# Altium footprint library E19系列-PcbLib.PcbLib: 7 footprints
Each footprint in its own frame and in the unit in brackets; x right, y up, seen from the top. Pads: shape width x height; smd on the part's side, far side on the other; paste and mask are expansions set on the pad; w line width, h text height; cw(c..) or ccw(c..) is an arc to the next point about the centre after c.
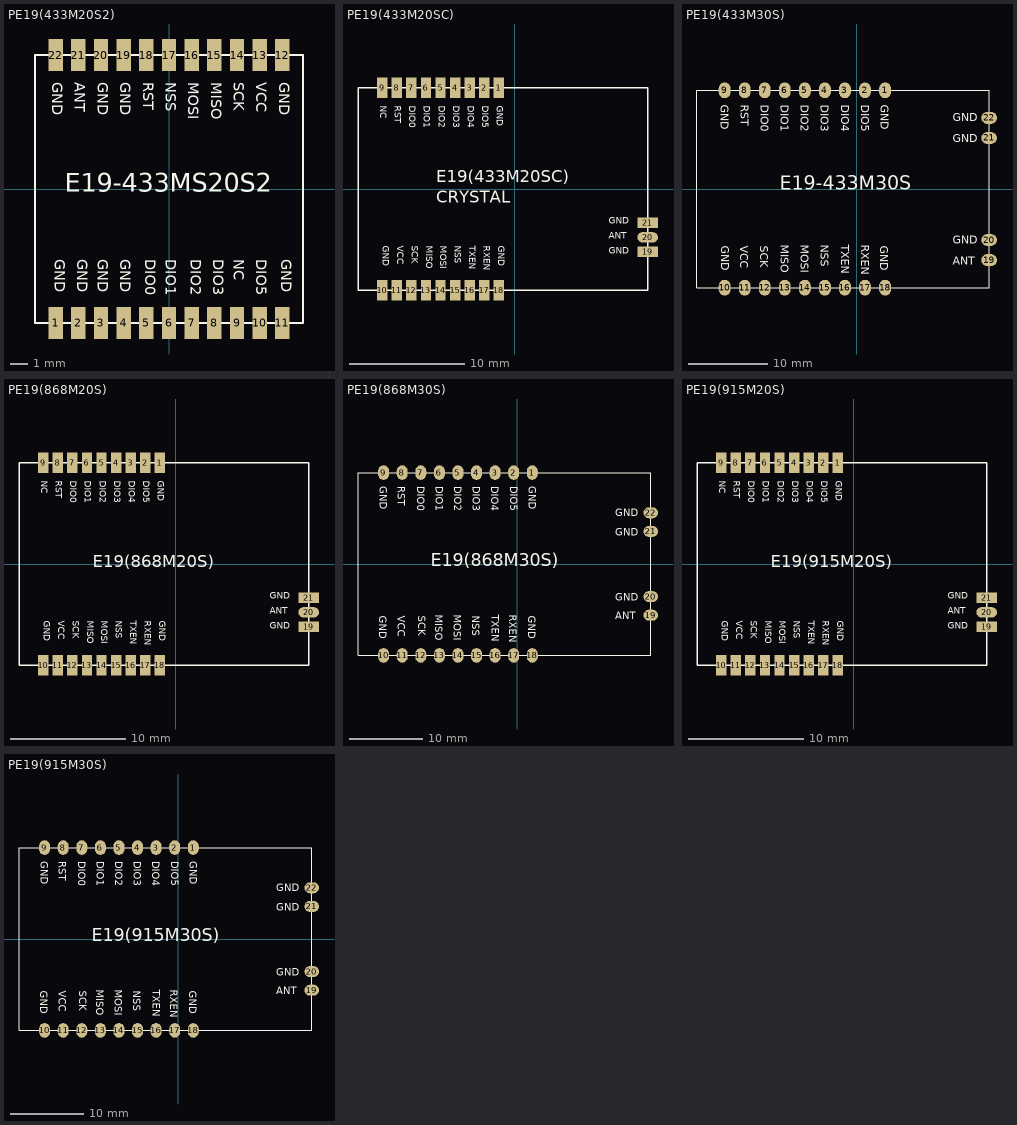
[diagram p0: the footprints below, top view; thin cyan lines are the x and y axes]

## PE19(433M20S2) [mm] "15mm*15mm*2.6mm-S"
pads (22):
  rect 0.8x1.8 smd: 1(-6.35,-7.5) 2(-5.08,-7.5) 3(-3.81,-7.5) 4(-2.54,-7.5) 5(-1.27,-7.5) 6(0,-7.5) 7(1.275,-7.5) 8(2.54,-7.5) 9(3.81,-7.5) 10(5.08,-7.5) 11(6.35,-7.5) 12(6.35,7.5) 13(5.08,7.5) 14(3.81,7.5) 15(2.54,7.5) 16(1.27,7.5) 17(0,7.5) 18(-1.275,7.5) 19(-2.54,7.5) 20(-3.81,7.5) 21(-5.08,7.5) 22(-6.35,7.5)
Top Overlay:
  lines w0.127: -7.5,-7.5 7.5,-7.5 7.5,7.5 -7.5,7.5 -7.5,-7.5
  text "E19-433MS20S2" at -5.842,-0.508 h1.8
  text "GND" at -6.604,-3.937 h1
  text "GND" at -5.334,-3.937 h1
  text "GND" at -4.191,-3.937 h1
  text "GND" at -2.921,-3.937 h1
  text "DIO0" at -1.524,-3.937 h1
  text "DIO1" at -0.381,-3.937 h1
  text "DIO2" at 1.016,-3.937 h1
  text "DIO3" at 2.286,-3.937 h1
  text "NC" at 3.429,-3.937 h1
  text "DIO5" at 4.699,-3.937 h1
  text "GND" at -6.731,5.969 h1
  text "ANT" at -5.461,5.969 h1
  text "GND" at -4.191,5.969 h1
  text "GND" at -2.921,5.969 h1
  text "RST" at -1.651,5.969 h1
  text "NSS" at -0.381,5.969 h1
  text "MISO" at 2.159,5.969 h1
  text "SCK" at 3.429,5.969 h1
  text "VCC" at 4.699,5.969 h1
  text "GND" at 5.969,5.969 h1
  text "GND" at 6.096,-3.937 h1
  text "MOSI" at 0.889,5.969 h1

## PE19(433M20SC) [mm] "25.2mm*17.6mm*3.8mm-S"
pads (21):
  rect 0.9x1.8 smd: 1(-1.39,8.8) 2(-2.66,8.8) 3(-3.93,8.8) 4(-5.2,8.8) 5(-6.47,8.8) 6(-7.74,8.8) 7(-9.01,8.8) 8(-10.28,8.8) 9(-11.55,8.8) 10(-11.55,-8.8) 11(-10.28,-8.8) 12(-9.01,-8.8) 13(-7.74,-8.8) 14(-6.47,-8.8) 15(-5.2,-8.8) 16(-3.93,-8.8) 17(-2.66,-8.8) 18(-1.39,-8.8)
  rect 1.8x0.9 smd: 19(11.55,-5.47) 21(11.55,-2.93)
  oval 1.8x0.9 smd: 20(11.55,-4.2)
Top Overlay:
  lines w0.127: -13.65,-8.8 11.55,-8.8 11.55,8.8 -13.65,8.8 -13.65,-8.8
  text "CRYSTAL" at -6.858,-1.524 h1.8
  text "E19(433M20SC)" at -6.858,0.254 h1.8
  text "GND" at -11.707,-4.924 h1
  text "VCC" at -10.455,-4.924 h1
  text "SCK" at -9.202,-4.924 h1
  text "MISO" at -7.95,-4.924 h1
  text "MOSI" at -6.697,-4.924 h1
  text "NSS" at -5.445,-4.924 h1
  text "TXEN" at -4.192,-4.924 h1
  text "RXEN" at -2.94,-4.924 h1
  text "GND" at -1.687,-4.924 h1
  text "NC" at -11.938,7.239 h1
  text "GND" at 8.158,-3.22 h1
  text "RST" at -10.668,7.239 h1
  text "DIO0" at -9.398,7.239 h1
  text "DIO1" at -8.128,7.239 h1
  text "DIO2" at -6.858,7.239 h1
  text "DIO3" at -5.588,7.239 h1
  text "DIO4" at -4.318,7.239 h1
  text "DIO5" at -3.048,7.239 h1
  text "GND" at -1.778,7.239 h1
  text "ANT" at 8.158,-4.53 h1
  text "GND" at 8.158,-5.84 h1

## PE19(433M30S) [mm]
pads (22):
  oval 1.5x2 smd: 1(3.57,12.5) 2(1.03,12.5) 3(-1.51,12.5) 4(-4.05,12.5) 5(-6.59,12.5) 6(-9.13,12.5) 7(-11.67,12.5) 8(-14.21,12.5) 9(-16.75,12.5) 10(-16.75,-12.5) 11(-14.21,-12.5) 12(-11.67,-12.5) 13(-9.13,-12.5) 14(-6.59,-12.5) 15(-4.05,-12.5) 16(-1.51,-12.5) 17(1.03,-12.5) 18(3.57,-12.5)
  oval 2x1.5 smd: 19(16.75,-9) 20(16.75,-6.46) 21(16.75,6.46) 22(16.75,9)
Top Overlay:
  lines w0.127: -20.25,-12.5 -20.25,12.5 16.75,12.5 16.75,-12.5 -20.25,-12.5
  text "GND" at 12.135,5.915 h1
  text "GND" at 12.135,8.582 h1
  text "ANT" at 12.135,-9.579 h1
  text "GND" at 12.135,-6.912 h1
  text "GND" at -17.25,10.691 h1
  text "RST" at -14.71,10.691 h1
  text "DIO0" at -12.17,10.691 h1
  text "DIO1" at -9.63,10.691 h1
  text "DIO2" at -7.09,10.691 h1
  text "DIO3" at -4.55,10.691 h1
  text "DIO4" at -2.01,10.691 h1
  text "DIO5" at 0.53,10.691 h1
  text "RXEN" at 0.53,-7.079 h1
  text "TXEN" at -2.01,-7.079 h1
  text "NSS" at -4.55,-7.079 h1
  text "MOSI" at -7.09,-7.079 h1
  text "MISO" at -9.63,-7.079 h1
  text "SCK" at -12.249,-7.166 h1
  text "VCC" at -14.789,-7.166 h1
  text "GND" at -17.202,-7.166 h1
  text "E19-433M30S" at -9.779,-0.635 h3
  text "GND" at 2.991,-7.166 h1
  text "GND" at 3.04,10.691 h1

## PE19(868M20S) [mm] "25.2mm*17.6mm*3.5mm-S"
pads (21):
  rect 0.9x1.8 smd: 1(-1.39,8.8) 2(-2.66,8.8) 3(-3.93,8.8) 4(-5.2,8.8) 5(-6.47,8.8) 6(-7.74,8.8) 7(-9.01,8.8) 8(-10.28,8.8) 9(-11.55,8.8) 10(-11.55,-8.8) 11(-10.28,-8.8) 12(-9.01,-8.8) 13(-7.74,-8.8) 14(-6.47,-8.8) 15(-5.2,-8.8) 16(-3.93,-8.8) 17(-2.66,-8.8) 18(-1.39,-8.8)
  rect 1.8x0.9 smd: 19(11.55,-5.47) 21(11.55,-2.93)
  oval 1.8x0.9 smd: 20(11.55,-4.2)
Top Overlay:
  lines w0.127: -13.65,-8.8 11.55,-8.8 11.55,8.8 -13.65,8.8 -13.65,-8.8
  text "E19(868M20S)" at -7.239,-0.635 h1.8
  text "GND" at -11.707,-4.924 h1
  text "VCC" at -10.455,-4.924 h1
  text "SCK" at -9.202,-4.924 h1
  text "MISO" at -7.95,-4.924 h1
  text "MOSI" at -6.697,-4.924 h1
  text "NSS" at -5.445,-4.924 h1
  text "TXEN" at -4.192,-4.924 h1
  text "RXEN" at -2.94,-4.924 h1
  text "GND" at -1.687,-4.924 h1
  text "NC" at -11.938,7.239 h1
  text "GND" at 8.158,-3.22 h1
  text "RST" at -10.668,7.239 h1
  text "DIO0" at -9.398,7.239 h1
  text "DIO1" at -8.128,7.239 h1
  text "DIO2" at -6.858,7.239 h1
  text "DIO3" at -5.588,7.239 h1
  text "DIO4" at -4.318,7.239 h1
  text "DIO5" at -3.048,7.239 h1
  text "GND" at -1.778,7.239 h1
  text "ANT" at 8.158,-4.53 h1
  text "GND" at 8.158,-5.84 h1

## PE19(868M30S) [mm] "40mm*25mm*4.85mm-S"
pads (22):
  oval 1.5x2 smd: 1(2.07,12.5) 2(-0.47,12.5) 3(-3.01,12.5) 4(-5.55,12.5) 5(-8.09,12.5) 6(-10.63,12.5) 7(-13.17,12.5) 8(-15.71,12.5) 9(-18.25,12.5) 10(-18.25,-12.5) 11(-15.71,-12.5) 12(-13.17,-12.5) 13(-10.63,-12.5) 14(-8.09,-12.5) 15(-5.55,-12.5) 16(-3.01,-12.5) 17(-0.47,-12.5) 18(2.07,-12.5)
  oval 2x1.5 smd: 19(18.25,-7) 20(18.25,-4.46) 21(18.25,4.46) 22(18.25,7)
Top Overlay:
  lines w0.127: -21.75,-12.5 18.25,-12.5 18.25,12.5 -21.75,12.5 -21.75,-12.5
  text "ANT" at 13.429,-7.547 h1
  text "GND" at 13.429,-5.007 h1
  text "GND" at 13.429,3.883 h1
  text "GND" at 13.429,6.55 h1
  text "RXEN" at -1.049,-6.912 h1
  text "TXEN" at -3.462,-6.912 h1
  text "NSS" at -6.129,-7.039 h1
  text "MOSI" at -8.669,-6.912 h1
  text "MISO" at -11.209,-6.912 h1
  text "SCK" at -13.495,-7.039 h1
  text "VCC" at -16.289,-7.039 h1
  text "GND" at -18.829,-7.039 h1
  text "DIO5" at -0.97,10.614 h1
  text "DIO4" at -3.51,10.614 h1
  text "DIO3" at -6.05,10.614 h1
  text "DIO2" at -8.59,10.614 h1
  text "DIO1" at -11.13,10.614 h1
  text "DIO0" at -13.67,10.614 h1
  text "RST" at -16.289,10.614 h1
  text "GND" at -18.75,10.614 h1
  text "GND" at 1.6,10.614 h1
  text "GND" at 1.491,-7.039 h1
  text "E19(868M30S)" at -11.811,-0.889 h3

## PE19(915M20S) [mm] "25.2mm*17.6mm*3.5mm-S"
pads (21):
  rect 0.9x1.8 smd: 1(-1.39,8.8) 2(-2.66,8.8) 3(-3.93,8.8) 4(-5.2,8.8) 5(-6.47,8.8) 6(-7.74,8.8) 7(-9.01,8.8) 8(-10.28,8.8) 9(-11.55,8.8) 10(-11.55,-8.8) 11(-10.28,-8.8) 12(-9.01,-8.8) 13(-7.74,-8.8) 14(-6.47,-8.8) 15(-5.2,-8.8) 16(-3.93,-8.8) 17(-2.66,-8.8) 18(-1.39,-8.8)
  rect 1.8x0.9 smd: 19(11.55,-5.47) 21(11.55,-2.93)
  oval 1.8x0.9 smd: 20(11.55,-4.2)
Top Overlay:
  lines w0.127: -13.65,-8.8 -13.65,8.8 11.55,8.8 11.55,-8.8 -13.65,-8.8
  text "GND" at 8.158,-5.84 h1
  text "ANT" at 8.158,-4.53 h1
  text "GND" at -1.778,7.239 h1
  text "DIO5" at -3.048,7.239 h1
  text "DIO4" at -4.318,7.239 h1
  text "DIO3" at -5.588,7.239 h1
  text "DIO2" at -6.858,7.239 h1
  text "DIO1" at -8.128,7.239 h1
  text "DIO0" at -9.398,7.239 h1
  text "RST" at -10.668,7.239 h1
  text "GND" at 8.158,-3.22 h1
  text "NC" at -11.938,7.239 h1
  text "GND" at -1.687,-4.924 h1
  text "RXEN" at -2.94,-4.924 h1
  text "TXEN" at -4.192,-4.924 h1
  text "NSS" at -5.445,-4.924 h1
  text "MOSI" at -6.697,-4.924 h1
  text "MISO" at -7.95,-4.924 h1
  text "SCK" at -9.202,-4.924 h1
  text "VCC" at -10.455,-4.924 h1
  text "GND" at -11.707,-4.924 h1
  text "E19(915M20S)" at -7.239,-0.635 h1.8

## PE19(915M30S) [mm] "40mm*25mm*4.85mm-S"
pads (22):
  oval 1.5x2 smd: 1(2.07,12.5) 2(-0.47,12.5) 3(-3.01,12.5) 4(-5.55,12.5) 5(-8.09,12.5) 6(-10.63,12.5) 7(-13.17,12.5) 8(-15.71,12.5) 9(-18.25,12.5) 10(-18.25,-12.5) 11(-15.71,-12.5) 12(-13.17,-12.5) 13(-10.63,-12.5) 14(-8.09,-12.5) 15(-5.55,-12.5) 16(-3.01,-12.5) 17(-0.47,-12.5) 18(2.07,-12.5)
  oval 2x1.5 smd: 19(18.25,-7) 20(18.25,-4.46) 21(18.25,4.46) 22(18.25,7)
Top Overlay:
  lines w0.127: -21.75,-12.5 -21.75,12.5 18.25,12.5 18.25,-12.5 -21.75,-12.5
  text "E19(915M30S)" at -11.811,-0.889 h3
  text "GND" at 1.491,-7.039 h1
  text "GND" at 1.6,10.614 h1
  text "GND" at -18.75,10.614 h1
  text "RST" at -16.289,10.614 h1
  text "DIO0" at -13.67,10.614 h1
  text "DIO1" at -11.13,10.614 h1
  text "DIO2" at -8.59,10.614 h1
  text "DIO3" at -6.05,10.614 h1
  text "DIO4" at -3.51,10.614 h1
  text "DIO5" at -0.97,10.614 h1
  text "GND" at -18.829,-7.039 h1
  text "VCC" at -16.289,-7.039 h1
  text "SCK" at -13.495,-7.039 h1
  text "MISO" at -11.209,-6.912 h1
  text "MOSI" at -8.669,-6.912 h1
  text "NSS" at -6.129,-7.039 h1
  text "TXEN" at -3.462,-6.912 h1
  text "RXEN" at -1.049,-6.912 h1
  text "GND" at 13.429,6.55 h1
  text "GND" at 13.429,3.883 h1
  text "GND" at 13.429,-5.007 h1
  text "ANT" at 13.429,-7.547 h1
